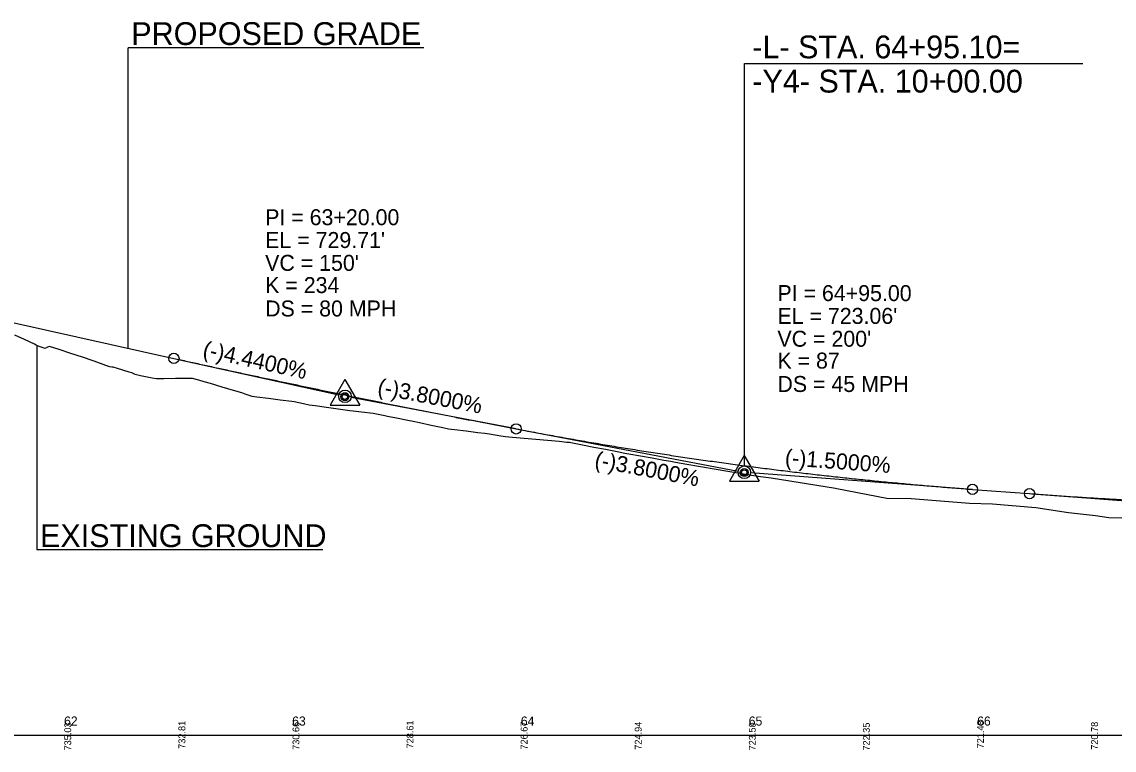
# Model space of a CAD drawing. Extents: x 1554255 to 1803987, y 659549 to 692876.
# Drawn here: x 1559972.1 to 1560450.8, y 692255.4 to 692574.5 of the extents above; entities that cross this region are included whole.
import ezdxf

# ---------------------------------------------------------------- set-up
doc = ezdxf.new("R2010")
doc.units = 0
for name, color, linetype in [('Default', 7, 'Continuous'), ('Exist Profile Cell', 7, 'Continuous'), ('Exist Vertical Profile Ground Line', 7, 'Continuous'), ('Prop PFL Text', 7, 'Continuous'), ('Prop PFL VPI Symbol CELL', 7, 'Continuous'), ('Prop Vertical Profile Curve Label', 7, 'Continuous'), ('Prop Vertical Profile Grade', 7, 'Continuous'), ('Prop Vertical Profile Grade Label', 7, 'Continuous'), ('Prop Vertical Profile Strip Grade', 7, 'Continuous'), ('Prop VPI Label', 7, 'Continuous')]:
    doc.layers.add(name, color=color, linetype=linetype)

msp = doc.modelspace()

# ---------------------------------------------------------------- linework, layer by layer
at = {"layer": 'Exist Profile Cell'}
msp.add_line((1554793.69, 692261.88), (1561762.5, 692261.88), dxfattribs=at)
at = {"layer": 'Exist Vertical Profile Ground Line'}
for p, q in [((1559973.18, 692435.26), (1559969.02, 692437.21)), ((1559977.55, 692433.23), (1559973.18, 692435.26)), ((1559978.27, 692432.87), (1559977.55, 692433.23)), ((1559979.63, 692432.21), (1559978.27, 692432.87)), ((1559982.24, 692431.41), (1559979.63, 692432.21)), ((1559983.37, 692431.96), (1559982.24, 692431.41)), ((1559984.11, 692432.32), (1559983.37, 692431.96)), ((1559988.46, 692430.87), (1559984.11, 692432.32)), ((1559993.56, 692429.19), (1559988.46, 692430.87)), ((1559998.65, 692427.54), (1559993.56, 692429.19)), ((1560003.33, 692426.04), (1559998.65, 692427.54)), ((1560003.75, 692425.88), (1560003.33, 692426.04)), ((1560008.84, 692423.98), (1560003.75, 692425.88)), ((1560010.69, 692423.3), (1560008.84, 692423.98)), ((1560011.43, 692423.24), (1560010.69, 692423.3)), ((1560012.03, 692423.22), (1560011.43, 692423.24)), ((1560013.94, 692422.63), (1560012.03, 692423.22)), ((1560019.03, 692421.07), (1560013.94, 692422.63)), ((1560020.27, 692420.7), (1560019.03, 692421.07)), ((1560021.74, 692419.93), (1560020.27, 692420.7)), ((1560024.12, 692419.45), (1560021.74, 692419.93)), ((1560029.22, 692418.44), (1560024.12, 692419.45)), ((1560031.12, 692418.06), (1560029.22, 692418.44)), ((1560034.31, 692418.11), (1560031.12, 692418.06)), ((1560039.41, 692418.17), (1560034.31, 692418.11)), ((1560044.5, 692418.21), (1560039.41, 692418.17)), ((1560046.79, 692418.22), (1560044.5, 692418.21)), ((1560049.6, 692417.43), (1560046.79, 692418.22)), ((1560051.9, 692416.77), (1560049.6, 692417.43)), ((1560054.69, 692415.97), (1560051.9, 692416.77)), ((1560059.78, 692414.48), (1560054.69, 692415.97)), ((1560064.88, 692412.99), (1560059.78, 692414.48)), ((1560068.53, 692411.91), (1560064.88, 692412.99)), ((1560069.97, 692411.42), (1560068.53, 692411.91)), ((1560073.02, 692410.38), (1560069.97, 692411.42)), ((1560075.07, 692410.12), (1560073.02, 692410.38)), ((1560080.16, 692409.46), (1560075.07, 692410.12)), ((1560085.26, 692408.8), (1560080.16, 692409.46)), ((1560090.35, 692408.13), (1560085.26, 692408.8)), ((1560091.48, 692407.98), (1560090.35, 692408.13)), ((1560095.44, 692407.13), (1560091.48, 692407.98)), ((1560098.05, 692406.57), (1560095.44, 692407.13)), ((1560100.54, 692406.22), (1560098.05, 692406.57)), ((1560105.63, 692405.5), (1560100.54, 692406.22)), ((1560110.73, 692404.78), (1560105.63, 692405.5)), ((1560115.82, 692404.05), (1560110.73, 692404.78)), ((1560117.22, 692403.85), (1560115.82, 692404.05)), ((1560120.92, 692403.43), (1560117.22, 692403.85)), ((1560126.01, 692402.86), (1560120.92, 692403.43)), ((1560126.72, 692402.77), (1560126.01, 692402.86)), ((1560131.1, 692401.85), (1560126.72, 692402.77)), ((1560132.37, 692401.58), (1560131.1, 692401.85)), ((1560136.2, 692400.83), (1560132.37, 692401.58)), ((1560141.29, 692399.83), (1560136.2, 692400.83)), ((1560143.56, 692399.38), (1560141.29, 692399.83)), ((1560146.39, 692398.77), (1560143.56, 692399.38)), ((1560151.48, 692397.67), (1560146.39, 692398.77)), ((1560156.58, 692396.57), (1560151.48, 692397.67)), ((1560159, 692396.03), (1560156.58, 692396.57)), ((1560161.67, 692395.71), (1560159, 692396.03)), ((1560166.76, 692395.1), (1560161.67, 692395.71)), ((1560171.86, 692394.47), (1560166.76, 692395.1)), ((1560174.91, 692394.09), (1560171.86, 692394.47)), ((1560176.95, 692393.78), (1560174.91, 692394.09)), ((1560182.05, 692393), (1560176.95, 692393.78)), ((1560183.97, 692392.71), (1560182.05, 692393)), ((1560185.48, 692392.52), (1560183.97, 692392.71)), ((1560187.14, 692392.38), (1560185.48, 692392.52)), ((1560192.24, 692391.94), (1560187.14, 692392.38)), ((1560197.33, 692391.5), (1560192.24, 692391.94)), ((1560202.42, 692391.04), (1560197.33, 692391.5)), ((1560207.52, 692390.57), (1560202.42, 692391.04)), ((1560210.94, 692390.25), (1560207.52, 692390.57)), ((1560211.32, 692390.2), (1560210.94, 692390.25)), ((1560212.11, 692390.14), (1560211.32, 692390.2)), ((1560212.61, 692390.04), (1560212.11, 692390.14)), ((1560217.71, 692389.05), (1560212.61, 692390.04)), ((1560222.8, 692388.05), (1560217.71, 692389.05)), ((1560227.9, 692387.06), (1560222.8, 692388.05)), ((1560232.99, 692386.07), (1560227.9, 692387.06)), ((1560236.31, 692385.42), (1560232.99, 692386.07)), ((1560238.08, 692385.1), (1560236.31, 692385.42)), ((1560243.18, 692384.19), (1560238.08, 692385.1)), ((1560248.27, 692383.27), (1560243.18, 692384.19)), ((1560253.37, 692382.35), (1560248.27, 692383.27)), ((1560256.44, 692381.8), (1560253.37, 692382.35)), ((1560258.46, 692381.44), (1560256.44, 692381.8)), ((1560263.56, 692380.54), (1560258.46, 692381.44)), ((1560268.65, 692379.64), (1560263.56, 692380.54)), ((1560272.13, 692379.03), (1560268.65, 692379.64)), ((1560273.74, 692378.76), (1560272.13, 692379.03)), ((1560291.79, 692375.79), (1560273.74, 692378.76)), ((1560295.78, 692375.14), (1560291.79, 692375.79)), ((1560300.42, 692374.52), (1560295.78, 692375.14)), ((1560328.61, 692370), (1560300.42, 692374.52)), ((1560329.28, 692369.89), (1560328.61, 692370)), ((1560351.14, 692365.67), (1560329.28, 692369.89)), ((1560361.75, 692365.46), (1560351.14, 692365.67)), ((1560374.74, 692364.53), (1560361.75, 692365.46)), ((1560387.41, 692363.4), (1560374.74, 692364.53)), ((1560397.45, 692363.17), (1560387.41, 692363.4)), ((1560416.48, 692361.49), (1560397.45, 692363.17)), ((1560430.72, 692359.44), (1560416.48, 692361.49)), ((1560442.63, 692358.01), (1560430.72, 692359.44)), ((1560448.5, 692357.14), (1560442.63, 692358.01)), ((1560454.07, 692357.03), (1560448.5, 692357.14))]:
    msp.add_line(p, q, dxfattribs=at)
at = {"layer": 'Prop PFL Text'}
for p, q in [((1560148.3, 692563.13), (1560018.69, 692563.13)), ((1560018.69, 692431.49), (1560018.69, 692563.13)), ((1560288.79, 692379.82), (1560288.79, 692556.24)), ((1560288.79, 692556.24), (1560437.1, 692556.24)), ((1559978.69, 692432.67), (1559978.69, 692343.13)), ((1560103.99, 692343.13), (1559978.69, 692343.13))]:
    msp.add_line(p, q, dxfattribs=at)
at = {"layer": 'Prop PFL VPI Symbol CELL'}
for p, q in [((1560113.64, 692417.75), (1560107.19, 692406.55)), ((1560113.64, 692417.75), (1560120.14, 692406.55)), ((1560107.19, 692406.55), (1560120.14, 692406.55)), ((1560288.64, 692384.5), (1560282.19, 692373.3)), ((1560288.64, 692384.5), (1560295.14, 692373.3)), ((1560282.19, 692373.3), (1560295.14, 692373.3))]:
    msp.add_line(p, q, dxfattribs=at)
for centre, radius in [((1560113.65, 692410.27), 1.75), ((1560113.65, 692410.27), 1.2), ((1560288.65, 692377.02), 1.75), ((1560288.65, 692377.02), 1.2)]:
    msp.add_circle(centre, radius, dxfattribs=at)
at = {"layer": 'Prop Vertical Profile Curve Label'}
for centre in [(1560038.69, 692427.05), (1560188.69, 692396.15), (1560188.69, 692396.15), (1560388.69, 692369.65), (1560413.69, 692367.78)]:
    msp.add_circle(centre, 2.25, dxfattribs=at)
at = {"layer": 'Prop Vertical Profile Grade'}
for p, q in [((1559968.69, 692442.59), (1560038.69, 692427.05)), ((1560388.69, 692369.65), (1560413.69, 692367.78))]:
    msp.add_line(p, q, dxfattribs=at)
for points in [[(1560038.69, 692427.05), (1560041.69, 692426.39), (1560044.69, 692425.72), (1560047.69, 692425.06), (1560050.69, 692424.4), (1560053.69, 692423.75), (1560056.69, 692423.09), (1560059.69, 692422.44), (1560062.69, 692421.79), (1560065.69, 692421.14), (1560068.69, 692420.49), (1560071.69, 692419.84), (1560074.69, 692419.2), (1560077.69, 692418.56), (1560080.69, 692417.92), (1560083.69, 692417.28), (1560086.69, 692416.64), (1560089.69, 692416.01), (1560092.69, 692415.38), (1560095.69, 692414.74), (1560098.69, 692414.12), (1560101.69, 692413.49), (1560104.69, 692412.86), (1560107.69, 692412.24), (1560110.69, 692411.62), (1560113.69, 692411), (1560116.69, 692410.39), (1560119.69, 692409.77), (1560122.69, 692409.16), (1560125.69, 692408.55), (1560128.69, 692407.94), (1560131.69, 692407.33), (1560134.69, 692406.72), (1560137.69, 692406.12), (1560140.69, 692405.52), (1560143.69, 692404.92), (1560146.69, 692404.32), (1560149.69, 692403.72), (1560152.69, 692403.13), (1560155.69, 692402.54), (1560158.69, 692401.95), (1560161.69, 692401.36), (1560164.69, 692400.77), (1560167.69, 692400.19), (1560170.69, 692399.61), (1560173.69, 692399.03), (1560176.69, 692398.45), (1560179.69, 692397.87), (1560182.69, 692397.3), (1560185.69, 692396.72), (1560188.69, 692396.15)], [(1560188.69, 692396.15), (1560192.69, 692395.4), (1560196.69, 692394.65), (1560200.69, 692393.91), (1560204.69, 692393.19), (1560208.69, 692392.47), (1560212.69, 692391.76), (1560216.69, 692391.06), (1560220.69, 692390.37), (1560224.69, 692389.68), (1560228.69, 692389.01), (1560232.69, 692388.35), (1560236.69, 692387.69), (1560240.69, 692387.05), (1560244.69, 692386.41), (1560248.69, 692385.79), (1560252.69, 692385.17), (1560256.69, 692384.56), (1560260.69, 692383.96), (1560264.69, 692383.37), (1560268.69, 692382.79), (1560272.69, 692382.22), (1560276.69, 692381.66), (1560280.69, 692381.11), (1560284.69, 692380.56), (1560288.69, 692380.03), (1560292.69, 692379.5), (1560296.69, 692378.99), (1560300.69, 692378.48), (1560304.69, 692377.98), (1560308.69, 692377.49), (1560312.69, 692377.01), (1560316.69, 692376.54), (1560320.69, 692376.08), (1560324.69, 692375.63), (1560328.69, 692375.19), (1560332.69, 692374.75), (1560336.69, 692374.33), (1560340.69, 692373.91), (1560344.69, 692373.51), (1560348.69, 692373.11), (1560352.69, 692372.72), (1560356.69, 692372.35), (1560360.69, 692371.98), (1560364.69, 692371.62), (1560368.69, 692371.27), (1560372.69, 692370.93), (1560376.69, 692370.59), (1560380.69, 692370.27), (1560384.69, 692369.96), (1560388.69, 692369.65)], [(1560413.69, 692367.78), (1560417.69, 692367.48), (1560421.69, 692367.19), (1560425.69, 692366.91), (1560429.69, 692366.64), (1560433.69, 692366.38), (1560437.69, 692366.13), (1560441.69, 692365.88), (1560445.69, 692365.64), (1560449.69, 692365.41), (1560453.69, 692365.19), (1560457.69, 692364.98), (1560461.69, 692364.77), (1560465.69, 692364.57), (1560469.69, 692364.38), (1560473.69, 692364.2), (1560477.69, 692364.03), (1560481.69, 692363.87), (1560485.69, 692363.71), (1560489.69, 692363.56), (1560493.69, 692363.42), (1560497.69, 692363.29), (1560501.69, 692363.17), (1560505.69, 692363.05), (1560509.69, 692362.95), (1560513.69, 692362.85), (1560517.69, 692362.76), (1560521.69, 692362.68), (1560525.69, 692362.6), (1560529.69, 692362.54), (1560533.69, 692362.48), (1560537.69, 692362.43), (1560541.69, 692362.39), (1560545.69, 692362.36), (1560549.69, 692362.33), (1560553.69, 692362.32), (1560557.69, 692362.31), (1560561.69, 692362.31), (1560565.69, 692362.32), (1560569.69, 692362.33), (1560573.69, 692362.36), (1560577.69, 692362.39), (1560581.69, 692362.43), (1560585.69, 692362.48), (1560589.69, 692362.54), (1560593.69, 692362.61), (1560597.69, 692362.68), (1560601.69, 692362.76), (1560605.69, 692362.86), (1560609.69, 692362.95), (1560613.69, 692363.06)]]:
    msp.add_spline(points, degree=3, dxfattribs=at)
at = {"layer": 'Prop VPI Label'}
for p, q in [((1560038.69, 692427.05), (1560111, 692411)), ((1560188.69, 692396.15), (1560116.39, 692409.89)), ((1560188.69, 692396.15), (1560285.99, 692377.67)), ((1560388.69, 692369.65), (1560291.43, 692376.95)), ((1560413.69, 692367.78), (1560510.95, 692360.48))]:
    msp.add_line(p, q, dxfattribs=at)
for centre in [(1560113.69, 692410.4), (1560288.69, 692377.15)]:
    msp.add_circle(centre, 2.75, dxfattribs=at)

# ---------------------------------------------------------------- texts
at = {"layer": 'Default'}
for s, p in [('62', (1559990.55, 692266.13)), ('63', (1560090.52, 692266.13)), ('64', (1560190.73, 692266.13)), ('65', (1560290.62, 692266.13)), ('66', (1560390.73, 692266.13))]:
    msp.add_text(s, height=4, dxfattribs=at).set_placement(p)
at = {"layer": 'Prop PFL Text'}
for s, p in [('PROPOSED GRADE', (1560020.03, 692564.35)), ('-L- STA. 64+95.10=', (1560292.2, 692558.51)), ('-Y4- STA. 10+00.00', (1560292.2, 692543.51)), ('EXISTING GROUND', (1559980.03, 692344.35))]:
    msp.add_text(s, height=10, rotation=360, dxfattribs=at).set_placement(p)
at = {"layer": 'Prop Vertical Profile Curve Label'}
for s, p in [("VC = 150'", (1560078.69, 692465.4)), ('K = 234', (1560078.69, 692455.66)), ('DS = 80 MPH', (1560078.69, 692445.41)), ("VC = 200'", (1560303.2, 692432.15)), ('K = 87', (1560303.2, 692422.57)), ('DS = 45 MPH', (1560303.2, 692412.32))]:
    msp.add_text(s, height=7, dxfattribs=at).set_placement(p)
at = {"layer": 'Prop Vertical Profile Grade Label'}
for s, rotation, p in [('(-)4.4400%', 347.4833, (1560050.96, 692427.9)), ('(-)3.8000%', 349.242, (1560127.59, 692411.43)), ('(-)1.5000%', 355.7108, (1560306.33, 692380.26)), ('(-)3.8000%', 349.242, (1560222.73, 692379.51))]:
    msp.add_text(s, height=7, rotation=rotation, dxfattribs=at).set_placement(p)
at = {"layer": 'Prop Vertical Profile Strip Grade'}
for s, p in [('735.03', (1559993.69, 692255.25)), ('732.81', (1560043.69, 692255.97)), ('730.66', (1560093.69, 692255.5)), ('728.61', (1560143.69, 692256.14)), ('726.67', (1560193.69, 692255.64)), ('724.94', (1560243.69, 692255.57)), ('723.50', (1560293.69, 692255.26)), ('722.35', (1560343.69, 692255.18)), ('721.48', (1560393.69, 692256.15)), ('720.78', (1560443.69, 692255.56))]:
    msp.add_text(s, height=3, rotation=90, dxfattribs=at).set_placement(p)
at = {"layer": 'Prop VPI Label'}
for s, p in [('PI = 63+20.00', (1560078.69, 692485.4)), ("EL = 729.71'", (1560078.69, 692475.4)), ('PI = 64+95.00', (1560303.2, 692452.15)), ("EL = 723.06'", (1560303.2, 692442.15))]:
    msp.add_text(s, height=7, dxfattribs=at).set_placement(p)

doc.saveas('drawing.dxf')
